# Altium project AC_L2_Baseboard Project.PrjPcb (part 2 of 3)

## Sheet AC_L2_Baseboard SCH-POL_PWR.SchDoc
size 431 x 279 mm; Date: Not shown in title block; ApprovedBy: Not shown in title block; CheckedBy: Not shown in title block; Author: Not shown in title block; CompanyName: Not shown in title block; Engineer: Not shown in title block; Organization: Not shown in title block; Address1: Not shown in title block; Address2: Not shown in title block; Address3: Not shown in title block; Address4: Not shown in title block; DocumentNumber: 3; Revision: Use project parameter SCH_Rev; SheetNumber: 3; SheetTotal: 11; PageSetup: Record=PageOptions¦CenterHorizontal=True¦CenterVertical=True¦PrintScale=1.00¦XCorrection=1.00¦YCorrection=1.00¦PrintKind=0¦BorderSize=5000000¦LeftOffset=0¦BottomOffset=0¦Orientation=2¦PaperLength=1000¦PaperWidth=1000¦Scale=100¦PaperSource=15¦PrintQuality=600¦MediaType=1¦DitherType=10¦PaperKind=Letter¦PrintScaleMode=1
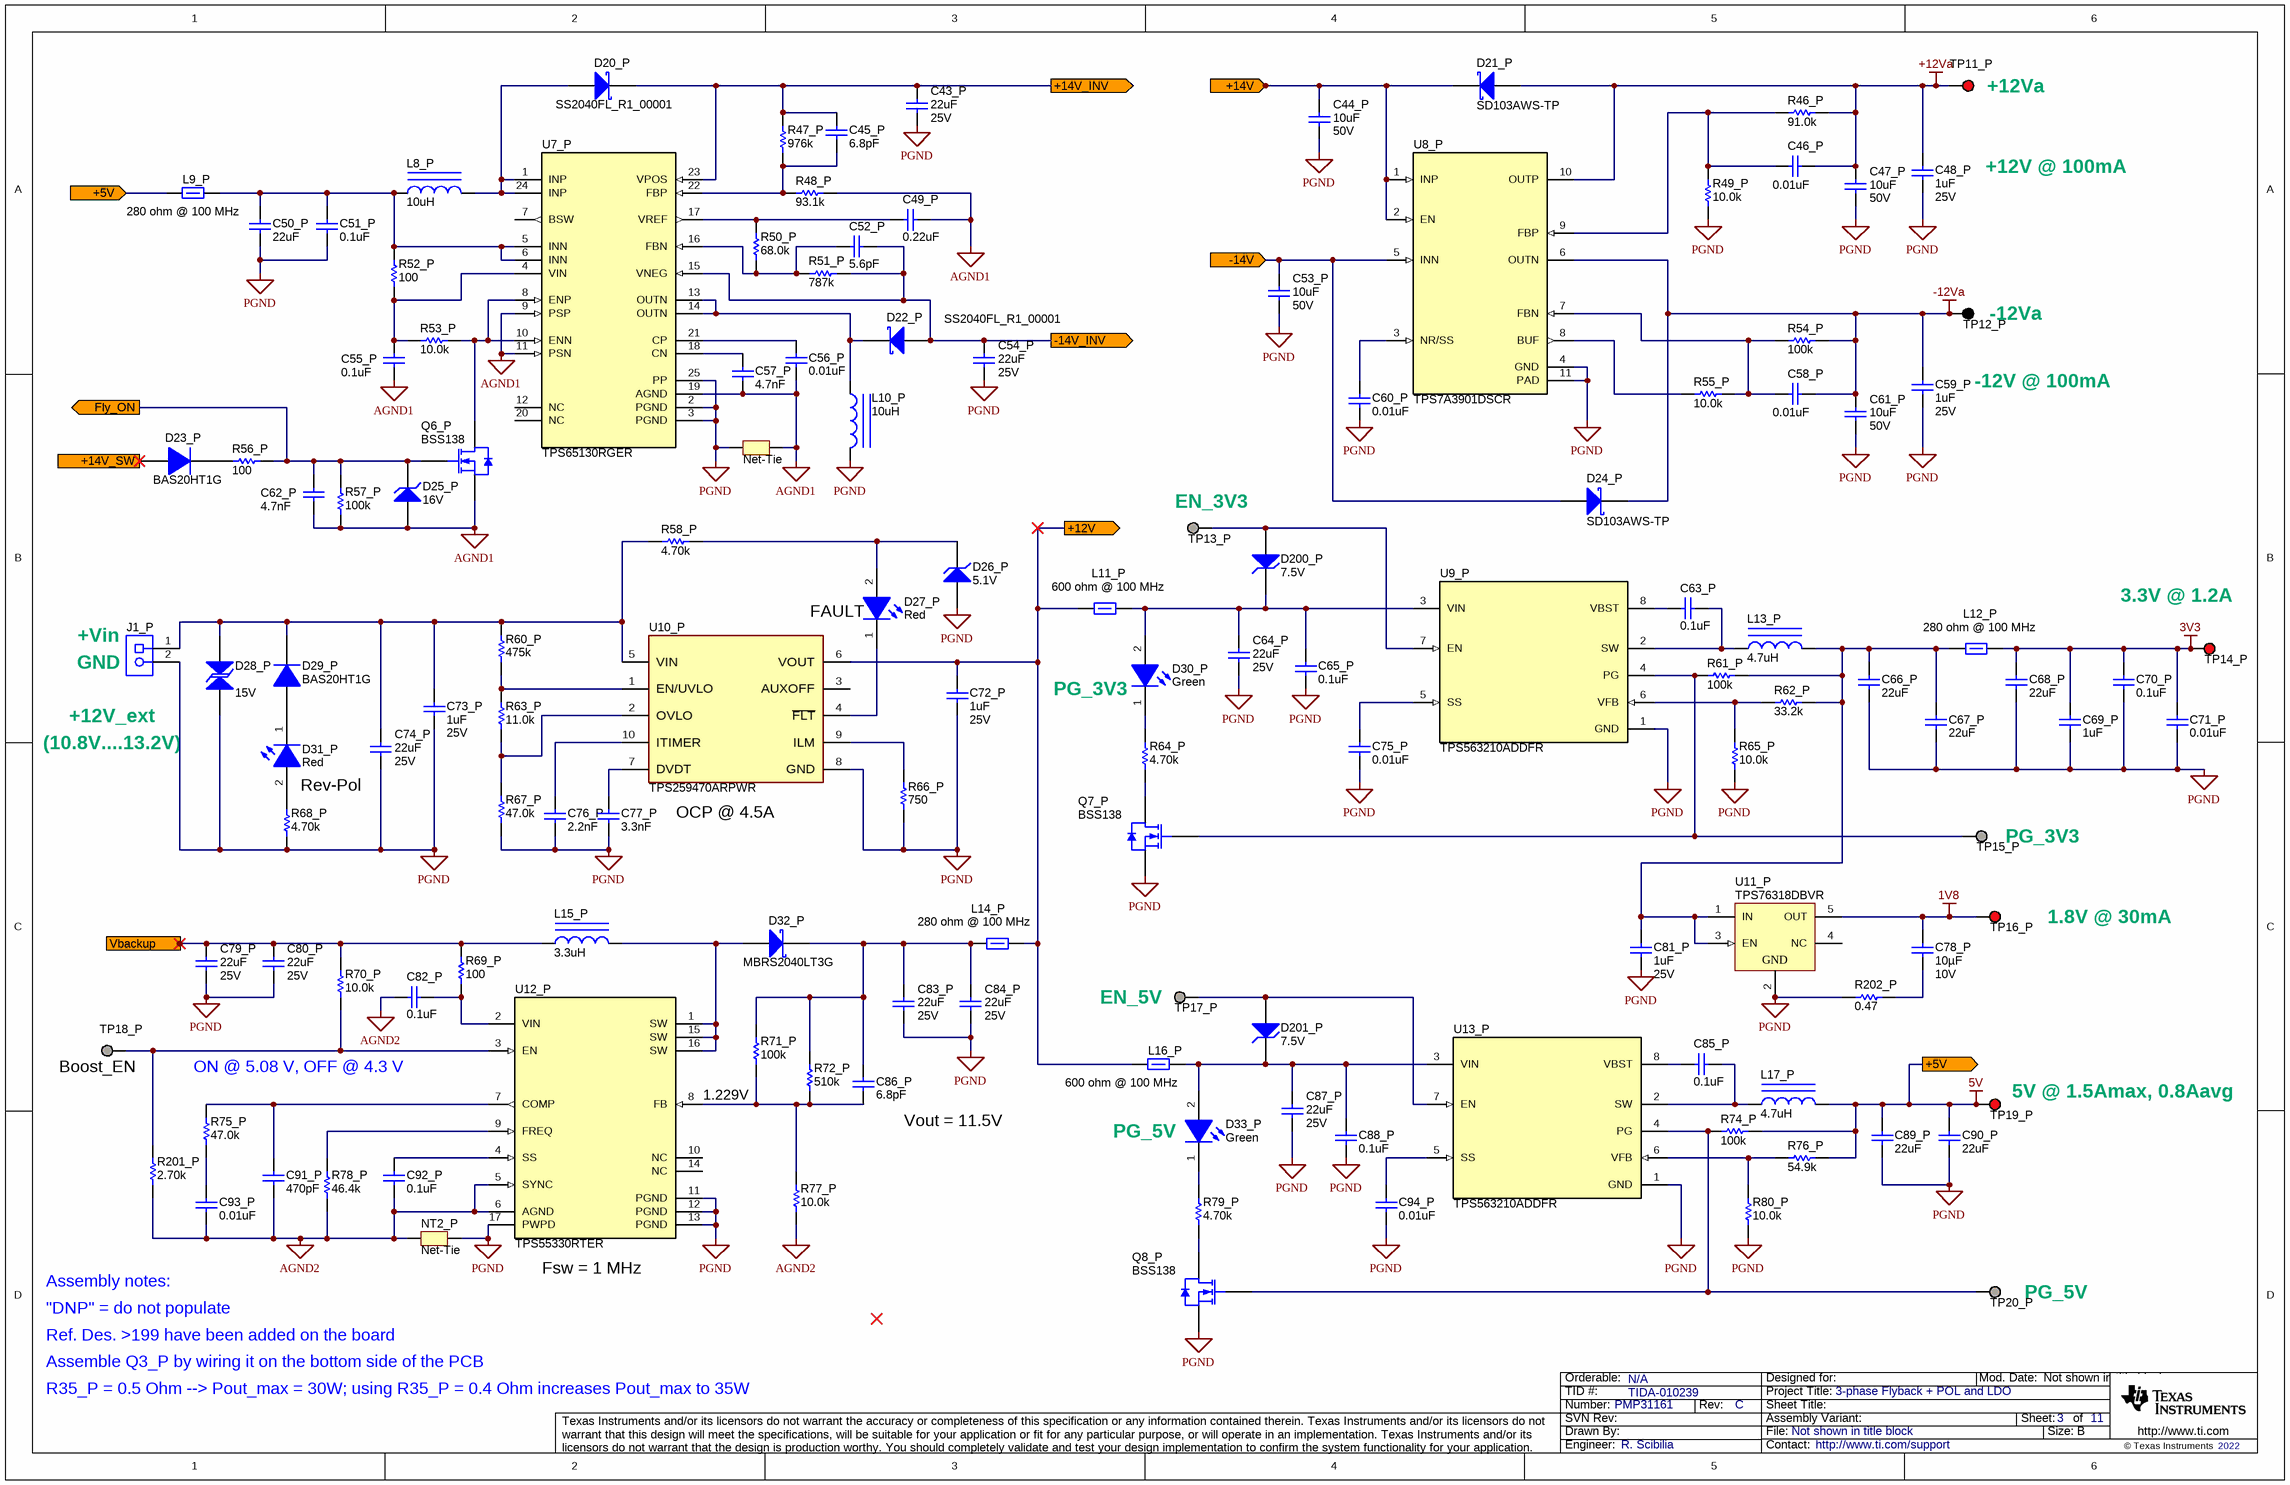
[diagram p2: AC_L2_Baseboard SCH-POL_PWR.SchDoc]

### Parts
C43_P  VDC_V: 25V  ValueDisplayed: 22uF  [1210_270]  (hidden comment: 885012109015)
C44_P  VDC_V: 50V  ValueDisplayed: 10uF  [1206]  (hidden comment: 885012108022)
C45_P  ValueDisplayed: 6.8pF  [0603]  (hidden comment: 885012006050)
C46_P  value 0.01uF  [0603]  (hidden comment: 885012206089)
C47_P  VDC_V: 50V  ValueDisplayed: 10uF  [1206]  (hidden comment: 885012108022)
C48_P  value 1uF  VDC_V: 25V  [0603]  (hidden comment: 885012206076)
C49_P  value 0.22uF  [0603]  (hidden comment: 885012206048)
C50_P  ValueDisplayed: 22uF  [1206_190]  (hidden comment: 885012208019)
C51_P  value 0.1uF  [0603]  (hidden comment: 885012206095)
C52_P  ValueDisplayed: 5.6pF  [0603]  (hidden comment: 885012006092)
C53_P  VDC_V: 50V  ValueDisplayed: 10uF  [1206]  (hidden comment: 885012108022)
C54_P  VDC_V: 25V  ValueDisplayed: 22uF  [1210_270]  (hidden comment: 885012109015)
C55_P  value 0.1uF  [0603]  (hidden comment: 885012206095)
C56_P  value 0.01uF  [0603]  (hidden comment: 885012206089)
C57_P  Cap_F: 4.7nF  [0603]  (hidden comment: 885012206087)
C58_P  value 0.01uF  [0603]  (hidden comment: 885012206089)
C59_P  value 1uF  VDC_V: 25V  [0603]  (hidden comment: 885012206076)
C60_P  value 0.01uF  [0603]  (hidden comment: 885012206089)
C61_P  VDC_V: 50V  ValueDisplayed: 10uF  [1206]  (hidden comment: 885012108022)
C62_P  Cap_F: 4.7nF  [0603]  (hidden comment: 885012206087)
C63_P  value 0.1uF  [0603]  (hidden comment: 885012206095)
C64_P  VDC_V: 25V  ValueDisplayed: 22uF  [1210_270]  (hidden comment: 885012109015)
C65_P  value 0.1uF  [0603]  (hidden comment: 885012206095)
C66_P  ValueDisplayed: 22uF  [1206_190]  (hidden comment: 885012208019)
C67_P  ValueDisplayed: 22uF  [1206_190]  (hidden comment: 885012208019)
C68_P  ValueDisplayed: 22uF  [1206_190]  (hidden comment: 885012208019)
C69_P  value 1uF  [0603]  (hidden comment: 885012206076)
C70_P  value 0.1uF  [0603]  (hidden comment: 885012206095)
C71_P  value 0.01uF  [0603]  (hidden comment: 885012206089)
C72_P  value 1uF  VDC_V: 25V  [0603]  (hidden comment: 885012206076)
C73_P  value 1uF  VDC_V: 25V  [0603]  (hidden comment: 885012206076)
C74_P  VDC_V: 25V  ValueDisplayed: 22uF  [1210_270]  (hidden comment: 885012109015)
C75_P  value 0.01uF  [0603]  (hidden comment: 885012206089)
C76_P  Cap_F: 2.2nF  [0603]  (hidden comment: 885012206085)
C77_P  Cap_F: 3.3nF  [0603]  (hidden comment: 885012206111)
C78_P  ValueDisplayed: 10µF  VDC_V: 10V  [0603]  (hidden comment: GRM188R61A106KE69D)
C79_P  VDC_V: 25V  ValueDisplayed: 22uF  [1210_270]  (hidden comment: 885012109015)
C80_P  VDC_V: 25V  ValueDisplayed: 22uF  [1210_270]  (hidden comment: 885012109015)
C81_P  value 1uF  VDC_V: 25V  [0603]  (hidden comment: 885012206076)
C82_P  value 0.1uF  [0603]  (hidden comment: 885012206095)
C83_P  VDC_V: 25V  ValueDisplayed: 22uF  [1210_270]  (hidden comment: 885012109015)
C84_P  VDC_V: 25V  ValueDisplayed: 22uF  [1210_270]  (hidden comment: 885012109015)
C85_P  value 0.1uF  [0603]  (hidden comment: 885012206095)
C86_P  ValueDisplayed: 6.8pF  [0603]  (hidden comment: 885012006050)
C87_P  VDC_V: 25V  ValueDisplayed: 22uF  [1210_270]  (hidden comment: 885012109015)
C88_P  value 0.1uF  [0603]  (hidden comment: 885012206095)
C89_P  ValueDisplayed: 22uF  [1206_190]  (hidden comment: 885012208019)
C90_P  ValueDisplayed: 22uF  [1206_190]  (hidden comment: 885012208019)
C91_P  Cap_F: 470pF  [0603]  (hidden comment: 885012206081)
C92_P  value 0.1uF  [0603]  (hidden comment: 885012206095)
C93_P  value 0.01uF  [0603]  (hidden comment: 885012206089)
C94_P  value 0.01uF  [0603]  (hidden comment: 885012206089)
D20_P  SS2040FL_R1_00001  [SOD-123FL]
D21_P  SD103AWS-TP  [SOD-323]
D22_P  SS2040FL_R1_00001  [SOD-123FL]
D23_P  BAS20HT1G  [SOD-323]
D24_P  SD103AWS-TP  [SOD-323]
D25_P  value 16V  [SOD-323]  (hidden comment: SZMM3Z16VST1G)
D26_P  value 5.1V  [SOD-323]  (hidden comment: BZT52C5V1S-7-F)
D27_P  value Red  [WL_SMCW_RED_1206]  (hidden comment: 150120RS75000)
D28_P  value 15V  [SMA_Bi]  (hidden comment: SMAJ15CA)
D29_P  BAS20HT1G  [SOD-323]
D30_P  value Green  [WL_SMCW_RED_1206]  (hidden comment: 150120GS75000)
D31_P  value Red  [WL_SMCW_RED_1206]  (hidden comment: 150120RS75000)
D32_P  MBRS2040LT3G  [SMB]
D33_P  value Green  [WL_SMCW_RED_1206]  (hidden comment: 150120GS75000)
D200_P  value 7.5V  [SOD-323]  (hidden comment: MM3Z7V5ST1G)
D201_P  value 7.5V  [SOD-323]  (hidden comment: MM3Z7V5ST1G)
J1_P  691214110002  [Wurth_691214110002]  (value not drawn)
L8_P  ValueDisplayed: 10uH  [WE-TPC-M1]  (hidden comment: 744042100)
L9_P  value 280 ohm @ 100 MHz  [1206]  (hidden comment: 74279221281)
L10_P  ValueDisplayed: 10uH  [WE-TPC-M1]  (hidden comment: 744042100)
L11_P  value 600 ohm @ 100 MHz  [1206_180]  (hidden comment: 74279221601)
L12_P  value 280 ohm @ 100 MHz  [1206]  (hidden comment: 74279221281)
L13_P  ValueDisplayed: 4.7uH  [WE-HC4]  (hidden comment: 744311470)
L14_P  value 280 ohm @ 100 MHz  [1206]  (hidden comment: 74279221281)
L15_P  ValueDisplayed: 3.3uH  [XEL4030_310]  (hidden comment: XEL4030-332MEB)
L16_P  value 600 ohm @ 100 MHz  [1206_180]  (hidden comment: 74279221601)
L17_P  ValueDisplayed: 4.7uH  [WE-HC4]  (hidden comment: 744311470)
NT1_P  Net-Tie  [Net-Tie_10mil]  (net tie, no BOM)
NT2_P  Net-Tie  [Net-Tie_10mil]  (net tie, no BOM)
Q6_P  BSS138  [SOT-23]
Q7_P  BSS138  [SOT-23]
Q8_P  BSS138  [SOT-23]
R46_P  ValueDisplayed: 91.0k  [0603]  (hidden comment: RC0603FR-0791KL)
R47_P  ValueDisplayed: 976k  [0603]  (hidden comment: CRCW0603976KFKEA)
R48_P  ValueDisplayed: 93.1k  [0603]  (hidden comment: CRCW060393K1FKEA)
R49_P  ValueDisplayed: 10.0k  [0603]  (hidden comment: RC0603FR-0710KL)
R50_P  ValueDisplayed: 68.0k  [0603]  (hidden comment: RC0603FR-0768KL)
R51_P  ValueDisplayed: 787k  [0603]  (hidden comment: RC0603FR-07787KL)
R52_P  ValueDisplayed: 100  [0603]  (hidden comment: CRCW0603100RFKEA)
R53_P  ValueDisplayed: 10.0k  [0603]  (hidden comment: RC0603FR-0710KL)
R54_P  ValueDisplayed: 100k  [0603]  (hidden comment: CRCW0603100KFKEA)
R55_P  ValueDisplayed: 10.0k  [0603]  (hidden comment: RC0603FR-0710KL)
R56_P  ValueDisplayed: 100  [0805_HV]  (hidden comment: CRCW0805100RFKEA)
R57_P  ValueDisplayed: 100k  [0603]  (hidden comment: CRCW0603100KFKEA)
R58_P  ValueDisplayed: 4.70k  [0603]  (hidden comment: RC0603FR-074K7L)
R60_P  ValueDisplayed: 475k  [0603]  (hidden comment: CRCW0603475KFKEA)
R61_P  ValueDisplayed: 100k  [0603S]  (hidden comment: CRCW0603100KFKEA)
R62_P  ValueDisplayed: 33.2k  [0603]  (hidden comment: RC0603FR-0733K2L)
R63_P  ValueDisplayed: 11.0k  [0603]  (hidden comment: RMCF0603FT11K0)
R64_P  ValueDisplayed: 4.70k  [0603]  (hidden comment: RC0603FR-074K7L)
R65_P  ValueDisplayed: 10.0k  [0603]  (hidden comment: RC0603FR-0710KL)
R66_P  ValueDisplayed: 750  [0603]  (hidden comment: CRCW0603750RFKEA)
R67_P  ValueDisplayed: 47.0k  [0603]  (hidden comment: RC0603FR-0747KL)
R68_P  ValueDisplayed: 4.70k  [0603]  (hidden comment: RC0603FR-074K7L)
R69_P  ValueDisplayed: 100  [0603]  (hidden comment: CRCW0603100RFKEA)
R70_P  ValueDisplayed: 10.0k  [0603]  (hidden comment: RC0603FR-0710KL)
R71_P  ValueDisplayed: 100k  [0603]  (hidden comment: RC0603FR-07100KL)
R72_P  ValueDisplayed: 510k  [0603]  (hidden comment: RC0603FR-07510KL)
R74_P  ValueDisplayed: 100k  [0603]  (hidden comment: CRCW0603100KFKEA)
R75_P  ValueDisplayed: 47.0k  [0603]  (hidden comment: RC0603FR-0747KL)
R76_P  ValueDisplayed: 54.9k  [0603]  (hidden comment: RC0603FR-0754K9L)
R77_P  ValueDisplayed: 10.0k  [0603]  (hidden comment: RC0603FR-0710KL)
R78_P  ValueDisplayed: 46.4k  [0603]  (hidden comment: RT0603DRE0746K4L)
R79_P  ValueDisplayed: 4.70k  [0603]  (hidden comment: RC0603FR-074K7L)
R80_P  ValueDisplayed: 10.0k  [0603]  (hidden comment: RC0603FR-0710KL)
R201_P  ValueDisplayed: 2.70k  [0603]  (hidden comment: RC0603FR-072K7L)
R202_P  ValueDisplayed: 0.47  [0603]  (hidden comment: ERJ-3RQFR47V)
TP11_P  5000  [Keystone5000]  (value not drawn)
TP12_P  5001  [Keystone5001]  (value not drawn)
TP13_P  TP_SM_1MM  [TP_SM_1MM]  (value not drawn)  (no BOM)
TP14_P  5010  [Keystone5010]  (value not drawn)
TP15_P  TP_SM_1MM  [TP_SM_1MM]  (value not drawn)  (no BOM)
TP16_P  5010  [Keystone5010]  (value not drawn)
TP17_P  TP_SM_1MM  [TP_SM_1MM]  (value not drawn)  (no BOM)
TP18_P  TP_SM_1MM  [TP_SM_1MM]  (value not drawn)  (no BOM)
TP19_P  5010  [Keystone5010]  (value not drawn)
TP20_P  TP_SM_1MM  [TP_SM_1MM]  (value not drawn)  (no BOM)
U7_P  TPS65130RGER  [RGE0024B]
U8_P  TPS7A3901DSCR  [DSC0010J]
U9_P  TPS563210ADDFR  [DDF0008A_N]
U10_P  TPS259470ARPWR  [RPW0010A-MFG]
U11_P  TPS76318DBVR  [DBV0005A_N]
U12_P  TPS55330RTER  [RTE0016C_NV]
U13_P  TPS563210ADDFR  [DDF0008A_N]

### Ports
+5V (in), +5V (out), +12V (out), +14V (in), +14V_INV (out), +14V_SW (in), -14V (in), -14V_INV (out), Fly_ON (out), Vbackup (in)

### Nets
1V8: C78_P.1 TP16_P.1 U11_P.5(OUT)
3V3: C68_P.1 C69_P.1 C70_P.1 C71_P.2 L12_P.2 TP14_P.1
5V: C89_P.1 C90_P.1 L9_P.1 L17_P.2 R74_P.2 R76_P.2 TP19_P.1 ; port +5V
+12Va: C46_P.2 C47_P.1 C48_P.1 D21_P.2(A) R46_P.1 TP11_P.1 U8_P.10(OUTP)
-12Va: C58_P.2 C59_P.1 C61_P.1 D24_P.1(K) R54_P.2 TP12_P.1 U8_P.6(OUTN)
AGND1: C49_P.1 C55_P.2 C56_P.1 C57_P.2 C62_P.2 D25_P.2(A) NT1_P.2 Q6_P.2(S) R48_P.2 R57_P.1 U7_P.9(PSP) U7_P.11(PSN) U7_P.19(AGND)
AGND2: C82_P.1 C91_P.2 C92_P.2 C93_P.1 NT2_P.1 R77_P.1 R78_P.1 R201_P.1 U12_P.5(SYNC) U12_P.6(AGND)
PGND: C43_P.2 C44_P.2 C47_P.2 C48_P.2 C50_P.2 C51_P.2 C53_P.2 C54_P.2 C59_P.2 C60_P.1 C61_P.2 C64_P.2 C65_P.2 C66_P.2 C67_P.2 C68_P.2 C69_P.2 C70_P.2 C71_P.1 C72_P.2 C73_P.2 C74_P.2 C75_P.1 C76_P.2 C77_P.2 C79_P.2 C80_P.2 C81_P.2 C83_P.2 C84_P.2 C87_P.2 C88_P.2 C89_P.2 C90_P.2 C94_P.1 D26_P.2(A) D28_P.1 J1_P.2 L10_P.2 NT1_P.1 NT2_P.2 Q7_P.2(S) Q8_P.2(S) R49_P.1 R65_P.1 R66_P.1 R67_P.1 R68_P.1 R80_P.1 R202_P.1 U7_P.2(PGND) U7_P.3(PGND) U7_P.25(PP) U8_P.4(GND) U8_P.11(PAD) U9_P.1(GND) U10_P.8(GND) U11_P.2(GND) U12_P.11(PGND) U12_P.12(PGND) U12_P.13(PGND) U12_P.17(PWPD) U13_P.1(GND)
+12V: C72_P.1 L11_P.1 L14_P.2 L16_P.1 U10_P.6(VOUT) ; port +12V
+14V: C44_P.1 D21_P.1(K) U8_P.1(INP) U8_P.2(EN) ; port +14V
+14V_INV: C43_P.1 C45_P.1 D20_P.1(K) R47_P.2 U7_P.23(VPOS) ; port +14V_INV
+14V_SW: D23_P.2(A) ; port +14V_SW
-14V: C53_P.1 D24_P.2(A) U8_P.5(INN) ; port -14V
-14V_INV: C52_P.1 C54_P.1 D22_P.2(A) R51_P.2 U7_P.15(VNEG) ; port -14V_INV
Fly_ON: C62_P.1 D25_P.1(K) Q6_P.1(G) R56_P.2 R57_P.2 ; port Fly_ON
Vbackup: C79_P.1 C80_P.1 L15_P.1 R69_P.2 R70_P.2 ; port Vbackup
NetC45_P_2: C45_P.2 R47_P.1 R48_P.1 U7_P.22(FBP)
NetC46_P_1: C46_P.1 R46_P.2 R49_P.2 U8_P.9(FBP)
NetC49_P_2: C49_P.2 R50_P.2 U7_P.17(VREF)
NetC50_P_1: C50_P.1 C51_P.1 L8_P.1 L9_P.2 R52_P.2 U7_P.5(INN) U7_P.6(INN)
NetC52_P_2: C52_P.2 R50_P.1 R51_P.1 U7_P.16(FBN)
NetC55_P_1: C55_P.1 R52_P.1 R53_P.2 U7_P.4(VIN)
NetC56_P_2: C56_P.2 U7_P.21(CP)
NetC57_P_1: C57_P.1 U7_P.18(CN)
NetC58_P_1: C58_P.1 R54_P.1 R55_P.2 U8_P.7(FBN)
NetC60_P_2: C60_P.2 U8_P.3(NR/SS)
NetC63_P_1: C63_P.1 U9_P.8(VBST)
NetC63_P_2: C63_P.2 L13_P.1 U9_P.2(SW)
NetC64_P_1: C64_P.1 C65_P.1 D30_P.2(A) D200_P.1(K) L11_P.2 U9_P.3(VIN)
NetC66_P_1: C66_P.1 C67_P.1 C81_P.1 L12_P.1 L13_P.2 R61_P.2 R62_P.2 U11_P.1(IN) U11_P.3(EN)
NetC73_P_1: C73_P.1 C74_P.1 D28_P.2 D29_P.1(K) J1_P.1 R58_P.2 R60_P.2 U10_P.5(VIN)
NetC75_P_2: C75_P.2 U9_P.5(SS)
NetC76_P_1: C76_P.1 U10_P.10(ITIMER)
NetC77_P_1: C77_P.1 U10_P.7(DVDT)
NetC78_P_2: C78_P.2 R202_P.2
NetC82_P_2: C82_P.2 R69_P.1 U12_P.2(VIN)
NetC83_P_1: C83_P.1 C84_P.1 C86_P.1 D32_P.1(K) L14_P.1 R71_P.2 R72_P.2
NetC85_P_1: C85_P.1 U13_P.8(VBST)
NetC85_P_2: C85_P.2 L17_P.1 U13_P.2(SW)
NetC86_P_2: C86_P.2 R71_P.1 R72_P.1 R77_P.2 U12_P.8(FB)
NetC87_P_1: C87_P.1 C88_P.1 D33_P.2(A) D201_P.1(K) L16_P.2 U13_P.3(VIN)
NetC91_P_1: C91_P.1 R75_P.2 U12_P.7(COMP)
NetC92_P_1: C92_P.1 U12_P.4(SS)
NetC93_P_2: C93_P.2 R75_P.1
NetC94_P_2: C94_P.2 U13_P.5(SS)
NetD20_P_2: D20_P.2(A) L8_P.2 U7_P.1(INP) U7_P.24(INP)
NetD22_P_1: D22_P.1(K) L10_P.1 U7_P.13(OUTN) U7_P.14(OUTN)
NetD23_P_1: D23_P.1(K) R56_P.1
NetD26_P_1: D26_P.1(K) D27_P.2(A) R58_P.1
NetD27_P_1: D27_P.1(K) U10_P.4(~{FLT})
NetD29_P_2: D29_P.2(A) D31_P.1(K)
NetD30_P_1: D30_P.1(K) R64_P.2
NetD31_P_2: D31_P.2(A) R68_P.2
NetD32_P_2: D32_P.2(A) L15_P.2 U12_P.1(SW) U12_P.15(SW) U12_P.16(SW)
NetD33_P_1: D33_P.1(K) R79_P.2
NetD200_P_2: D200_P.2(A) TP13_P.1 U9_P.7(EN)
NetD201_P_2: D201_P.2(A) TP17_P.1 U13_P.7(EN)
NetQ6_P_3: Q6_P.3(D) R53_P.1 U7_P.8(ENP) U7_P.10(ENN)
NetQ7_P_1: Q7_P.1(G) R61_P.1 TP15_P.1 U9_P.4(PG)
NetQ7_P_3: Q7_P.3(D) R64_P.1
NetQ8_P_1: Q8_P.1(G) R74_P.1 TP20_P.1 U13_P.4(PG)
NetQ8_P_3: Q8_P.3(D) R79_P.1
NetR55_P_1: R55_P.1 U8_P.8(BUF)
NetR60_P_1: R60_P.1 R63_P.2 U10_P.1(EN/UVLO)
NetR62_P_1: R62_P.1 R65_P.2 U9_P.6(VFB)
NetR63_P_1: R63_P.1 R67_P.2 U10_P.2(OVLO)
NetR66_P_2: R66_P.2 U10_P.9(ILM)
NetR70_P_1: R70_P.1 R201_P.2 TP18_P.1 U12_P.3(EN)
NetR76_P_1: R76_P.1 R80_P.2 U13_P.6(VFB)
NetR78_P_2: R78_P.2 U12_P.9(FREQ)

Not connected (* = marked no-connect by the designer): U7_P 7(BSW) 12(NC) 20(NC); U10_P 3(AUXOFF); U11_P 4(NC); U12_P 10(NC) 14(NC)

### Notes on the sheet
- (near TP11_P) +12Va
- +12V @ 100mA
- (near TP12_P) -12Va
- -12V @ 100mA
- (near TP13_P) EN_3V3
- (near J1_P) +Vin
- FAULT
- (near TP14_P) 3.3V @ 1.2A
- (near J1_P) GND
- (near D30_P) PG_3V3
- (near J1_P) +12V_ext
- (10.8V....13.2V)
- Rev-Pol
- (near U10_P) OCP @ 4.5A
- (near TP15_P) PG_3V3
- 1.8V @ 30mA
- (near TP17_P) EN_5V
- (near TP18_P) Boost_EN
- ON @ 5.08 V, OFF @ 4.3 V
- 1.229V
- (near TP19_P) 5V @ 1.5Amax, 0.8Aavg
- (near C86_P) Vout = 11.5V
- (near D33_P) PG_5V
- Assembly notes:
- (near U12_P) Fsw = 1 MHz
- (near TP20_P) PG_5V
- Ref. Des. >199 have been added on the board
- Assemble Q3_P by wiring it on the bottom side of the PCB
- "DNP" = do not populate
- R35_P = 0.5 Ohm --> Pout_max = 30W; using R35_P = 0.4 Ohm increases Pout_max to 35W

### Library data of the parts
C43_P C54_P C64_P C74_P C79_P C80_P C83_P C84_P C87_P = CMP-0009224-2: CAP, CERM, 22 uF, 25 V, +/- 20%, X5R, 1210; Manufacturer: Wuerth; TaMin_C: -55°C; Polarized: N; SizeAreaWB_mm2: 14.7; Value1: Unknown; U/M: EA; Value: 22uF; TaMax_C: 85°C; SizeZ_mm: 2.7; SizeX_mm: 3.2; SizeY_mm: 2.5; Cap_Case: 1210; SizeArea_mm2: 8; Cap_F: 22µF; AEC Category: Q200
C44_P C47_P C53_P C61_P = CMP-0008821-2: CAP, CERM, 10 uF, 50 V, +/- 10%, X7R, 1206; Manufacturer: Wuerth; TaMin_C: -55°C; Polarized: N; SizeAreaWB_mm2: 10.92; Value1: Unknown; U/M: EA; Value: 10uF; TaMax_C: 125°C; SizeZ_mm: 1.35; SizeX_mm: 3.2; SizeY_mm: 1.6; SizeArea_mm2: 5.12; Cap_F: 10µF; AEC Category: Q200
C45_P C86_P = CMP-0006798-4: CAP, CERM, 6.8 pF, 50 V, +/- 4%, C0G/NP0, 0603; Manufacturer: Wuerth; TaMin_C: -55°C; ESR_ohm: 0.505; Polarized: N; SizeAreaWB_mm2: 4.68; Value1: 0.505 ohm; U/M: EA; Value: 6.8pF; TaMax_C: 125°C; SizeZ_mm: 1; SizeX_mm: 1.6; SizeY_mm: 0.8; Value2: 50V; SizeArea_mm2: 1.28; AEC Category: Q200
C46_P C56_P C58_P C60_P C71_P C75_P C93_P C94_P = CMP-0006854-4: CAP, CERM, 0.01 uF, 50 V, +/- 10%, X7R, 0603; Manufacturer: Wuerth; TaMin_C: -55°C; Polarized: N; SizeAreaWB_mm2: 4.68; U/M: EA; TaMax_C: 125°C; SizeZ_mm: 1; SizeX_mm: 1.6; SizeY_mm: 0.8; Value2: 50V; SizeArea_mm2: 1.28; Cap_F: 10nF; AEC Category: Q200
C48_P C59_P C72_P C73_P C81_P = CMP-0083856-1: CAP, CERM, 1 µF, 25 V,+/- 10%, X7R, 0603; Manufacturer: Wuerth; TaMin_C: -55°C; Polarized: N; SizeAreaWB_mm2: 4.68; U/M: EA; TaMax_C: 125°C; SizeZ_mm: 1; SizeX_mm: 1.6; SizeY_mm: 0.8; SizeArea_mm2: 1.28; Cap_F: 1µF; AEC Category: Q200
C49_P = CMP-0007389-4: CAP, CERM, 0.22 uF, 16 V, +/- 10%, X7R, 0603; Manufacturer: Wuerth; TaMin_C: -55°C; Polarized: N; SizeAreaWB_mm2: 4.68; Value1: Unknown; U/M: EA; TaMax_C: 125°C; SizeZ_mm: 1; SizeX_mm: 1.6; SizeY_mm: 0.8; Value2: 16V; SizeArea_mm2: 1.28; Cap_F: 220nF; AEC Category: Q200
C50_P C66_P C67_P C68_P C89_P C90_P = CMP-0064937-2: CAP, CERM, 22 uF, 10 V,+/- 10%, X7R, 1206; Manufacturer: Wurth Elektronik; TaMin_C: -55°C; Polarized: N; SizeAreaWB_mm2: 10.92; Value1: Unknown; U/M: EA; Value: 22uF; TaMax_C: 125°C; SizeZ_mm: 1.9; SizeX_mm: 3.2; SizeY_mm: 1.6; Cap_Case: 1206; Value2: 10V; SizeArea_mm2: 5.12; Cap_F: 22µF; AEC Category: Q200
C51_P C55_P C63_P C65_P C70_P C82_P C85_P C88_P C92_P = CMP-0007044-5: CAP, CERM, 0.1 uF, 50 V, +/- 10%, X7R, 0603; Manufacturer: Wuerth; TaMin_C: -55°C; ESR_ohm: 29.6m; Polarized: N; SizeAreaWB_mm2: 4.68; Value1: 0.0296 ohm; U/M: EA; TaMax_C: 125°C; SizeZ_mm: 1; SizeX_mm: 1.6; SizeY_mm: 0.8; Value2: 50V; SizeArea_mm2: 1.28; Cap_F: 100nF; IRMS_A: 971.99mA; AEC Category: Q200
C52_P = CMP-0006795-4: CAP, CERM, 5.6 pF, 50 V, +/- 5%, C0G/NP0, 0603; Manufacturer: Wuerth; TaMin_C: -55°C; ESR_ohm: 0.568; Polarized: N; SizeAreaWB_mm2: 4.68; Value1: 0.568 ohm; U/M: EA; Value: 5.6pF; TaMax_C: 125°C; SizeZ_mm: 1; SizeX_mm: 1.6; SizeY_mm: 0.8; Value2: 50V; SizeArea_mm2: 1.28; AEC Category: Q200
C57_P C62_P = CMP-0006835-4: CAP, CERM, 4700 pF, 50 V, +/- 10%, X7R, 0603; Manufacturer: Wurth Elektronik; TaMin_C: -55°C; Polarized: N; SizeAreaWB_mm2: 4.68; Value1: Unknown; U/M: EA; Value: 4700pF; TaMax_C: 125°C; SizeZ_mm: 1; SizeX_mm: 1.6; SizeY_mm: 0.8; Value2: 50V; SizeArea_mm2: 1.28; AEC Category: Q200
C69_P = CMP-0083856-1: CAP, CERM, 1 µF, 25 V,+/- 10%, X7R, 0603; Manufacturer: Wuerth; TaMin_C: -55°C; Polarized: N; SizeAreaWB_mm2: 4.68; U/M: EA; TaMax_C: 125°C; SizeZ_mm: 1; SizeX_mm: 1.6; SizeY_mm: 0.8; Value2: 25V; SizeArea_mm2: 1.28; Cap_F: 1µF; AEC Category: Q200
C76_P = CMP-0006897-4: CAP, CERM, 2200 pF, 50 V, +/- 10%, X7R, 0603; Manufacturer: Wuerth; TaMin_C: -55°C; Polarized: N; SizeAreaWB_mm2: 4.68; Value1: Unknown; U/M: EA; Value: 2200pF; TaMax_C: 125°C; SizeZ_mm: 1; SizeX_mm: 1.6; SizeY_mm: 0.8; Value2: 50V; SizeArea_mm2: 1.28; AEC Category: Q200
C77_P = CMP-0006805-4: CAP, CERM, 3300 pF, 50 V, +/- 10%, X7R, 0603; Manufacturer: Wuerth; TaMin_C: -55°C; Polarized: N; SizeAreaWB_mm2: 4.68; Value1: Unknown; U/M: EA; Value: 3300pF; TaMax_C: 125°C; SizeZ_mm: 1; SizeX_mm: 1.6; SizeY_mm: 0.8; Value2: 50V; SizeArea_mm2: 1.28; AEC Category: Q200
C78_P = CMP-0085855-1: CAP, CERM, 10 µF, 10 V,+/- 10%, X5R, 0603; Manufacturer: MuRata; SizeX_mm: 1.6; SizeAreaWB_mm2: 4.68; Green_REACh: Incomplete; AEC Category: Q200; SizeArea_mm2: 1.28; SizeY_mm: 0.8; Green_Lifecycle: Active; TaMax_C: 85°C; Value: 10uF; U/M: EA; Polarized: N; TaMin_C: -55°C; SizeZ_mm: 1
C91_P = CMP-0006834-5: CAP, CERM, 470 pF, 50 V, +/- 10%, X7R, 0603; Manufacturer: Wurth Elektronik; TaMin_C: -55°C; Polarized: N; SizeAreaWB_mm2: 4.68; Value1: Unknown; U/M: EA; Value: 470pF; TaMax_C: 125°C; SizeZ_mm: 1; SizeX_mm: 1.6; SizeY_mm: 0.8; Value2: 50V; SizeArea_mm2: 1.28; AEC Category: Q200
D20_P D22_P = CMP-0028777-2: Diode, Schottky, 40 V, 2 A, SOD-123FL; Manufacturer: Panjit International Inc.; Green_REACh: Incomplete; SizeArea_mm2: 5.94; Value1: 2A; AEC Qualified: Y; Value2: 0.63V; SizeZ_mm: 0.98; SizeAreaWB_mm2: 12.19; Vr_V: 40V; SizeY_mm: 1.65; SizeX_mm: 3.6; TJmax_C: 150°C; Green_Lifecycle: Not Set; AEC Category: Q101; Vf_V: 630mV
D21_P D24_P = CMP-0076928-2: Diode, Schottky, 40 V, 0.35 A, SOD-323; Manufacturer: Micro Commercial Components; SizeX_mm: 2.7; Vr_V: 40V; SizeAreaWB_mm2: 8.695; AEC Category: Q101; Vf_V: 600mV; SizeArea_mm2: 3.645; Green_Lifecycle: Not Set; SizeY_mm: 1.35; Io_A: 350mA; SizeZ_mm: 1.0; Green_REACh: Incomplete; Value2: 0.6V; Value1: 0.35A
D23_P D29_P = CMP-0029150-2: Diode, Switching, 200 V, 0.2 A, AEC-Q101, SOD-323; Manufacturer: ON Semiconductor; Value2: 1.25V; Value1: 0.2A; SizeZ_mm: 1; Green_REACh: Incomplete; SizeArea_mm2: 3.645; Vr_V: 200V; SizeX_mm: 2.7; TJmax_C: 150°C; Io_A: 200mA; Green_Lifecycle: Not Set; SizeAreaWB_mm2: 8.695; AEC Qualified: Y; AEC Category: Q101; SizeY_mm: 1.35
D25_P = CMP-0085759-1: Diode, Zener, 16 V, 300 mW, AEC-Q101, SOD-323; Manufacturer: ON Semiconductor; AEC Category: Q101; RJA_CperW: 416; SizeX_mm: 2.7; SizeAreaWB_mm2: 8.695; SizeZ_mm: 1; SizeArea_mm2: 3.645; AEC Qualified: Y; SizeY_mm: 1.35; Value1: 0.3W; Power_W: 300mW
D26_P = CMP-0005865-3: Diode, Zener, 5.1 V, 200 mW, SOD-323; Manufacturer: Diodes Inc.; SizeY_mm: 1.35; SizeX_mm: 2.7; RJA_CperW: 625; AEC Category: Q101; SizeArea_mm2: 3.645; Value1: 0.2W; SizeZ_mm: 1; SizeAreaWB_mm2: 8.695; Power_W: 200mW
D27_P D31_P = CMP-0002935-3: LED, Red, SMD; Manufacturer: Wurth Elektronik; Vf_V: 2V; Angle: 140; Value1: 0.072W; Vr_V: 5V; Io_A: 20mA; Tjmax_C: 85°C; Type: AlInGaP; Power_TotalModule: 72mW; Ir_A: 10µA
D28_P = CMP-0085006-1: Diode, TVS, Bi, 15 V, 24.4 Vc, 400 W, 16.4 A, SMA (non-polarized); Manufacturer: Littelfuse; RJA_CperW: 120; Vbr_Min: 16.7V; Value1: 24.4V; SizeAreaWB_mm2: 32.368125; Green_Lifecycle: Active; SizeArea_mm2: 13.068125; AEC Category: Q101; SizeX_mm: 5.075; SizeY_mm: 2.575; AEC Qualified: N; Ipp: 16.4A; Ppk: 400W; SizeZ_mm: 2.65; Green_REACh: Incomplete; Vbr_Max: 18.5V
D30_P D33_P = CMP-0002935-3: LED, Green, SMD; Manufacturer: Wurth Elektronik; Vf_V: 2V; Angle: 140; Value1: 0.072W; Vr_V: 5V; Io_A: 20mA; Tjmax_C: 85°C; Type: AlInGaP; Power_TotalModule: 72mW; Ir_A: 10µA
D32_P = CMP-0028529-2: Diode, Schottky, 40 V, 2 A, SMB; Manufacturer: ON Semiconductor; TJmax_C: 125°C; AEC Category: Q101; SizeY_mm: 3.81; Io_A: 2A; SizeX_mm: 5.6; Vf_V: 430mV; RJC_CperW: 22.5; Vr_V: 40V; SizeAreaWB_mm2: 44.156; SizeZ_mm: 2.6; Green_Lifecycle: Active; SizeArea_mm2: 21.336; Value2: 0.43V; Value: 40V; Green_REACh: Passed
D200_P D201_P = CMP-0085747-1: Diode, Zener, 7.5 V, 300 mW, SOD-323; Manufacturer: ON Semiconductor; AEC Category: Q101; Power_W: 300mW; RJA_CperW: 416; AEC Qualified: N; SizeArea_mm2: 3.645; SizeX_mm: 2.7; SizeY_mm: 1.35; SizeZ_mm: 1; SizeAreaWB_mm2: 8.695; Value1: 0.3W
J1_P = CMP-0054825-2: Terminal Block, 3.5mm, 2x1, Tin, TH; Manufacturer: Wurth Elektronik; Pitch_mm: 3.5; CT: TRUE; CNHeader: FALSE; Voltage_V: 300V; Gender: Female; Cert_UL: Y; Row_Count: 1; Current_A: 10A
L8_P L10_P = CMP-0063804-1: Inductor, Shielded Drum Core, Ferrite, 10 uH, 1 A, 0.12 ohm, SMD; Manufacturer: Wurth Elektronik; Isat: 1A @ 35% inductance drop; Irms: 1.3A @ 30C rise; Green_Lifecycle: Active; SizeAreaWB_mm2: 33.64; DCR_ohm: 0.12; Green_REACh: Passed; Value: 10uH; Imax_A: 1A; SizeZ_mm: 1.8; SizeX_mm: 4.8; SizeArea_mm2: 23.04; Ind_H: 10µH; AEC Category: Q200
L9_P L12_P L14_P = CMP-0003140-1: Ferrite Bead, 280 ohm @ 100 MHz, 3.5 A, 1206; Manufacturer: Wurth Elektronik; Ztyp@1GHz_Ohm: 79.415; ZTyp@100MHz_Ohm: 280; SizeAreaWB_mm2: 10.92; DCR_ohm: 22m; Value1: 0.022 ohm; Imax_A: 3.5A; SizeZ_mm: 1.35; SizeX_mm: 3.2; SizeY_mm: 1.6; SizeArea_mm2: 5.12; ValueDisplayed: 280 ohm
L11_P L16_P = CMP-0086103-1: Ferrite Bead, 600 ohm @ 100 MHz, 2.5 A, 1206; Manufacturer: Wuerth; DCR_ohm: 38m; SizeZ_mm: 1.8; Value1: 0.038 ohm; SizeAreaWB_mm2: 10.92; ZTyp@100MHz_Ohm: 600; SizeY_mm: 1.6; SizeArea_mm2: 5.12; Imax_A: 2.5A; SizeX_mm: 3.2; ValueDisplayed: 600 ohm
L13_P L17_P = CMP-0063928-1: Inductor, Shielded Drum Core, Superflux, 4.7 uH, 6 A, 0.02 ohm, SMD; Manufacturer: Wurth Elektronik; Isat: 7A @ 30% inductance drop; Irms: 6A @ 50C rise; Green_Lifecycle: Active; SizeAreaWB_mm2: 80.1; DCR_ohm: 20m; Green_REACh: Passed; Value: 4.7uH; Imax_A: 6A; SizeZ_mm: 4; SizeX_mm: 7; SizeY_mm: 6.9; SizeArea_mm2: 48.3; Ind_H: 4.7µH; AEC Category: Q200
L15_P = CMP-0061090-1: Inductor, Shielded, 3.3 uH, 5 A, 0.0286 ohm, SMD; Manufacturer: Coilcraft; Isat: 5.9A @ 30% inductance drop; Irms: 5A @ 20C rise; SizeAreaWB_mm2: 25; DCR_ohm: 28.6m; Value: 3.3uH; Imax_A: 5A; SizeZ_mm: 3.1; SizeX_mm: 4; SizeArea_mm2: 16; Ind_H: 3.3µH; AEC Qualified: N; AEC Category: Q200
NT1_P NT2_P = CMP-0078142-2: Single point connection between nets.
Q6_P Q7_P Q8_P = CMP-0000755-1: MOSFET, N-CH, 50 V, 0.22 A, SOT-23; Alternate Manufacturer: None; Manufacturer: Fairchild Semiconductor; SizeZ_mm: 1.1; ChType: N; Value2: 1.7 nC; VdsMax_V: 50V; SizeX_mm: 2.5; SizeY_mm: 3; Vgs_V: 20V; Rdson45_ohm: 6; SizeArea_mm2: 7.5; AEC Category: Q101; IdsMax_A: 220mA; SizeAreaWB_mm2: 14; U/M: EA; QgTyp_nC: 1.7
R46_P = CMP-0023318-5: RES, 91.0 k, 1%, 0.1 W, 0603; Manufacturer: Yageo; Power_W: 100mW; TempCo: 100 ppm/C; Value_Code: 91k0; Value: 91.0k; Res_ohm: 91k; SizeX_mm: 1.6; SizeY_mm: 0.8; SizeZ_mm: 1; Value2: 0.1W; SizeArea_mm2: 1.28; AEC Qualified: N; VDC_V: 75V; AEC Category: Q200; SizeAreaWB_mm2: 4.68
R47_P = CMP-0022661-3: RES, 976 k, 1%, 0.1 W, AEC-Q200 Grade 0, 0603; Manufacturer: Vishay-Dale; Power_W: 100mW; TempCo: 100 ppm/C; Value: 976k; EIA_Code: E96; SizeX_mm: 1.6; SizeY_mm: 0.8; SizeZ_mm: 1; Value2: 0.1W; SizeArea_mm2: 1.28; AEC Qualified: Y; VDC_V: 75V; AEC Category: Q200; AEC Grade: 0
R48_P = CMP-0022655-4: RES, 93.1 k, 1%, 0.1 W, AEC-Q200 Grade 0, 0603; Manufacturer: Vishay-Dale; Power_W: 100mW; TempCo: 100 ppm/C; Value_Code: 93k1; Value: 93.1k; EIA_Code: E96; SizeX_mm: 1.6; SizeY_mm: 0.8; SizeZ_mm: 1; Value2: 0.1W; SizeArea_mm2: 1.28; AEC Qualified: Y; VDC_V: 75V; AEC Category: Q200; AEC Grade: 0
R49_P R53_P R55_P R65_P R70_P R77_P R80_P = CMP-0022746-5: RES, 10.0 k, 1%, 0.1 W, 0603; Manufacturer: Yageo; Power_W: 100mW; TempCo: 100 ppm/C; Value_Code: 10k0; Value: 10.0k; EIA_Code: E96; Res_ohm: 10k; SizeX_mm: 1.6; SizeY_mm: 0.8; SizeZ_mm: 1; Value2: 0.1W; SizeArea_mm2: 1.28; AEC Qualified: N; VDC_V: 75V; AEC Category: Q200; SizeAreaWB_mm2: 4.68
R50_P = CMP-0023239-5: RES, 68.0 k, 1%, 0.1 W, 0603; Manufacturer: Yageo; Power_W: 100mW; TempCo: 100 ppm/C; Value_Code: 68k0; Value: 68.0k; Res_ohm: 68k; SizeX_mm: 1.6; SizeY_mm: 0.8; SizeZ_mm: 1; Value2: 0.1W; SizeArea_mm2: 1.28; AEC Qualified: N; VDC_V: 75V; AEC Category: Q200; SizeAreaWB_mm2: 4.68
R51_P = CMP-0023273-4: RES, 787 k, 1%, 0.1 W, 0603; Manufacturer: Yageo; Power_W: 100mW; TempCo: 100 ppm/C; Value: 787k; EIA_Code: E96; SizeX_mm: 1.6; SizeY_mm: 0.8; SizeZ_mm: 1; Value2: 0.1W; SizeArea_mm2: 1.28; AEC Qualified: N; VDC_V: 75V; AEC Category: Q200; SizeAreaWB_mm2: 4.68
R52_P R69_P = CMP-0021991-4: RES, 100, 1%, 0.1 W, AEC-Q200 Grade 0, 0603; Manufacturer: Vishay-Dale; Power_W: 100mW; TempCo: 100 ppm/C; Value_Code: 100R; Value: 100; EIA_Code: E96; SizeX_mm: 1.6; SizeY_mm: 0.8; SizeZ_mm: 1; Value2: 0.1W; SizeArea_mm2: 1.28; AEC Qualified: Y; VDC_V: 75V; AEC Category: Q200; AEC Grade: 0
R54_P R57_P R61_P R74_P = CMP-0021990-4: RES, 100 k, 1%, 0.1 W, AEC-Q200 Grade 0, 0603; Manufacturer: Vishay-Dale; Power_W: 100mW; TempCo: 100 ppm/C; Value: 100k; EIA_Code: E96; SizeX_mm: 1.6; SizeY_mm: 0.8; SizeZ_mm: 1; Value2: 0.1W; SizeArea_mm2: 1.28; AEC Qualified: Y; VDC_V: 75V; AEC Category: Q200; AEC Grade: 0
R56_P = CMP-0020835-3: RES, 100, 1%, 0.125 W, AEC-Q200 Grade 0, 0805; Manufacturer: Vishay-Dale; Power_W: 125mW; TempCo: 100 ppm/C; Value_Code: 100R; Value: 100; EIA_Code: E96; SizeX_mm: 2; SizeY_mm: 1.25; SizeZ_mm: 1.45; Value2: 0.125W; SizeArea_mm2: 2.5; AEC Qualified: Y; VDC_V: 150V; AEC Category: Q200; AEC Grade: 0
R58_P R64_P R68_P R79_P = CMP-0023153-5: RES, 4.70 k, 1%, 0.1 W, 0603; Manufacturer: Yageo; Power_W: 100mW; TempCo: 100 ppm/C; Value_Code: 4k70; Value: 4.70k; Res_ohm: 4.7k; SizeX_mm: 1.6; SizeY_mm: 0.8; SizeZ_mm: 1; Value2: 0.1W; SizeArea_mm2: 1.28; AEC Qualified: N; VDC_V: 75V; AEC Category: Q200; SizeAreaWB_mm2: 4.68
R60_P = CMP-0022436-4: RES, 475 k, 1%, 0.1 W, AEC-Q200 Grade 0, 0603; Manufacturer: Vishay-Dale; Power_W: 100mW; TempCo: 100 ppm/C; Value: 475k; EIA_Code: E96; SizeX_mm: 1.6; SizeY_mm: 0.8; SizeZ_mm: 1; Value2: 0.1W; SizeArea_mm2: 1.28; AEC Qualified: Y; VDC_V: 75V; AEC Category: Q200; AEC Grade: 0
R62_P = CMP-0023036-5: RES, 33.2 k, 1%, 0.1 W, 0603; Manufacturer: Yageo; Power_W: 100mW; TempCo: 100 ppm/C; Value_Code: 33k2; Value: 33.2k; EIA_Code: E96; SizeX_mm: 1.6; SizeY_mm: 0.8; SizeZ_mm: 1; Value2: 0.1W; SizeArea_mm2: 1.28; AEC Qualified: N; VDC_V: 75V; AEC Category: Q200; SizeAreaWB_mm2: 4.68
R63_P = CMP-0023342-3: RES, 11.0 k, 1%, 0.1 W, AEC-Q200 Grade 0, 0603; Manufacturer: Stackpole Electronics Inc; Power_W: 100mW; TempCo: 100 ppm/C; Value_Code: 11k0; U/M: EA; Value: 11.0k; EIA_Code: E96; Res_ohm: 11k; SizeX_mm: 1.6; SizeY_mm: 0.8; SizeZ_mm: 1; Value2: 0.1W; SizeArea_mm2: 1.28; AEC Qualified: Y; VDC_V: 75V; AEC Grade: 0; AEC Category: Q200
R66_P = CMP-0022588-5: RES, 750, 1%, 0.1 W, AEC-Q200 Grade 0, 0603; Manufacturer: Vishay-Dale; Power_W: 100mW; TempCo: 100 ppm/C; Value_Code: 750R; Value: 750; EIA_Code: E96; SizeX_mm: 1.6; SizeY_mm: 0.8; SizeZ_mm: 1; Value2: 0.1W; SizeArea_mm2: 1.28; AEC Qualified: Y; VDC_V: 75V; AEC Category: Q200; AEC Grade: 0
R67_P R75_P = CMP-0023133-5: RES, 47.0 k, 1%, 0.1 W, 0603; Manufacturer: Yageo; Power_W: 100mW; TempCo: 100 ppm/C; Value_Code: 47k0; Value: 47.0k; Res_ohm: 47k; SizeX_mm: 1.6; SizeY_mm: 0.8; SizeZ_mm: 1; Value2: 0.1W; SizeArea_mm2: 1.28; AEC Qualified: N; VDC_V: 75V; AEC Category: Q200; SizeAreaWB_mm2: 4.68
R71_P = CMP-0022735-5: RES, 100 k, 1%, 0.1 W, 0603; Manufacturer: Yageo; Power_W: 100mW; TempCo: 100 ppm/C; Value: 100k; EIA_Code: E96; SizeX_mm: 1.6; SizeY_mm: 0.8; SizeZ_mm: 1; Value2: 0.1W; SizeArea_mm2: 1.28; AEC Qualified: N; VDC_V: 75V; AEC Category: Q200; SizeAreaWB_mm2: 4.68
R72_P = CMP-0023162-4: RES, 510 k, 1%, 0.1 W, 0603; Manufacturer: Yageo; Power_W: 100mW; TempCo: 100 ppm/C; Value: 510k; SizeX_mm: 1.6; SizeY_mm: 0.8; SizeZ_mm: 1; Value2: 0.1W; SizeArea_mm2: 1.28; AEC Qualified: N; VDC_V: 75V; AEC Category: Q200; SizeAreaWB_mm2: 4.68
R76_P = CMP-0023180-5: RES, 54.9 k, 1%, 0.1 W, 0603; Manufacturer: Yageo; Power_W: 100mW; TempCo: 100 ppm/C; Value_Code: 54k9; Value: 54.9k; EIA_Code: E96; SizeX_mm: 1.6; SizeY_mm: 0.8; SizeZ_mm: 1; Value2: 0.1W; SizeArea_mm2: 1.28; AEC Qualified: N; VDC_V: 75V; AEC Category: Q200; SizeAreaWB_mm2: 4.68
R78_P = CMP-0025309-3: RES, 46.4 k, 0.5%, 0.1 W, 0603; Manufacturer: Yageo America; Power_W: 100mW; TempCo: 50 ppm/C; Value_Code: 46k4; U/M: EA; Value: 46.4k; EIA_Code: E192; SizeX_mm: 1.6; SizeY_mm: 0.8; SizeZ_mm: 1; Value2: 0.1W; SizeArea_mm2: 1.28; VDC_V: 75V; AEC Category: Q200
R201_P = CMP-0022996-5: RES, 2.70 k, 1%, 0.1 W, 0603; Manufacturer: Yageo; Power_W: 100mW; TempCo: 100 ppm/C; Value_Code: 2k70; Value: 2.70k; Res_ohm: 2.7k; SizeX_mm: 1.6; SizeY_mm: 0.8; SizeZ_mm: 1; Value2: 0.1W; SizeArea_mm2: 1.28; AEC Qualified: N; VDC_V: 75V; AEC Category: Q200; SizeAreaWB_mm2: 4.68
R202_P = CMP-0022716-3: RES, 0.47, 1%, 0.1 W, AEC-Q200 Grade 0, 0603; Manufacturer: Panasonic; Power_W: 100mW; TempCo: 300 ppm/C; Value_Code: R470; Value: 0.47; EIA_Code: E96; SizeX_mm: 1.6; SizeY_mm: 0.8; SizeZ_mm: 1; Value2: 0.1W; SizeArea_mm2: 1.28; AEC Qualified: Y; AEC Category: Q200; AEC Grade: 0; SizeAreaWB_mm2: 4.68
TP11_P = CMP-0055137-2: Test Point, Miniature, Red, TH; Manufacturer: Keystone Electronics; Green_REACh: Passed; Green_Lifecycle: Active; ContactFinish: Silver; CNHeader: FALSE; CT: TRUE
TP12_P = CMP-0055138-2: Test Point, Miniature, Black, TH; Manufacturer: Keystone Electronics; ContactFinish: Silver; CNHeader: FALSE; Green_Lifecycle: Active; Green_REACh: Passed; CT: TRUE
TP13_P TP15_P TP17_P TP18_P TP20_P = CMP-0003825-1: 1mm Test Point, SMT; Manufacturer: Any
TP14_P TP16_P TP19_P = CMP-0055147-2: Test Point, Multipurpose, Red, TH; Manufacturer: Keystone Electronics; CT: TRUE; ContactFinish: Silver; Green_Lifecycle: Active; CNHeader: FALSE; Green_REACh: Passed
U7_P = CMP-0034952-2: Postive and Negative Output DC-DC Converter, 2.7 to 5.5 V, -40 to 85 degC, 24-pin QFN (RGE24), Green (RoHS & no Sb/Br); Manufacturer: Texas Instruments; SubFamily: LCD/OLED Display Bias Solutions; Rating: Catalog; Topology: Boost, Inverting Buck/Boost; Vin(Max)(V): 5.5; Vin(Min)(V): 2.7; Iq(Typ)(mA): 0.5; Switching Frequency(Typ)(kHz): 1400
U8_P = CMP-0013435-7: Dual, 150mA, Wide-Vin, Positive and Negative Low-Dropout (LDO) Voltage Regulator, DSC0010J (WSON-10); Alternate Manufacturer: Texas Instruments; Alternate PartNumber: TPS7A3901DSCT; Rating: Catalog; CompType: IC; SizeAreaWB_mm2: 16.0; SizeY_mm: 3.0; AEC Qualified: N; SizeZ_mm: 0.8; SizeArea_mm2: 9.0; AEC Category: Q200
U9_P U13_P = CMP-0013290-3: 17V Input, 3A Synchronous Step-Down Regulator in SOT-23 w/ Advanced Eco-mode™, PG, Soft Start, DDF0008A (SOT-23-THN-8); Alternate Manufacturer: Texas Instruments; Alternate PartNumber: TPS563210ADDFT; AEC Category: Q200; SizeZ_mm: 1.1; SizeAreaWB_mm2: 14.82; Rating: Catalog; CompType: IC; SizeX_mm: 2.8; AEC Qualified: N; SizeY_mm: 2.9; SizeArea_mm2: 8.12
U10_P = CMP-0091660-1: 2.7 - 23 V, 5.5 A, 28 mΩ True Reverse Current Blocking eFuse with Input Reverse Polarity Protection; Manufacturer: Texas Instruments; Min Supply Voltage: 2.7V; TJmax_C: +125°C; Nominal Supply Current: 428uA; Max Supply Voltage: 23V; SizeZ_mm: 1mm; AEC Qualified: No; Standoff Height: 0mm; Number Of Outputs: 1
U11_P = CMP-0035639-1: Single Output LDO, 150 mA, Fixed 1.8 V Output, 2.7 to 10 V Input, with Low IQ, 5-pin SOT-23 (DBV), -40 to 125 degC, Green (RoHS & no Sb/Br); Manufacturer: Texas Instruments; Vin(Max)(V): 10; SubFamily: Single Channel LDO; Vout Adj(Min)(V): 1.8; Accuracy(%): 3; Iq(Typ)(mA): 0.08; Iout(Max)(A): 0.15; Vin(Min)(V): 2.7; Vdo(Typ)(mV): 300
U12_P = CMP-0067160-2: Integrated 5-A 24-V Wide Input Range Boost/SEPIC/Flyback DC-DC Regulator, RTE0016C (WQFN-16); Alternate PartNumber: TPS55330RTET; Manufacturer: Texas Instruments; SizeZ_mm: 0.8; SizeX_mm: 3.0; SizeArea_mm2: 9.0; CompType: IC; U/M: EA; SizeAreaWB_mm2: 16.0

## Sheet AC_L2_Baseboard_Relay_Weld_Detect.SchDoc
size 431 x 279 mm; Date: Not shown in title block; ApprovedBy: Not shown in title block; CheckedBy: Not shown in title block; Author: Not shown in title block; CompanyName: Not shown in title block; Engineer: Not shown in title block; Organization: Not shown in title block; Address1: Not shown in title block; Address2: Not shown in title block; Address3: Not shown in title block; Address4: Not shown in title block; DocumentNumber: 4; Revision: Use project parameter SCH_Rev; SheetNumber: 4; SheetTotal: 11; PageSetup: Record=PageOptions¦CenterHorizontal=True¦CenterVertical=True¦PrintScale=1.00¦XCorrection=1.00¦YCorrection=1.00¦PrintKind=0¦BorderSize=5000000¦LeftOffset=0¦BottomOffset=0¦Orientation=2¦PaperLength=1000¦PaperWidth=1000¦Scale=100¦PaperSource=15¦PrintQuality=600¦MediaType=1¦DitherType=10¦PaperKind=Letter¦PrintScaleMode=1
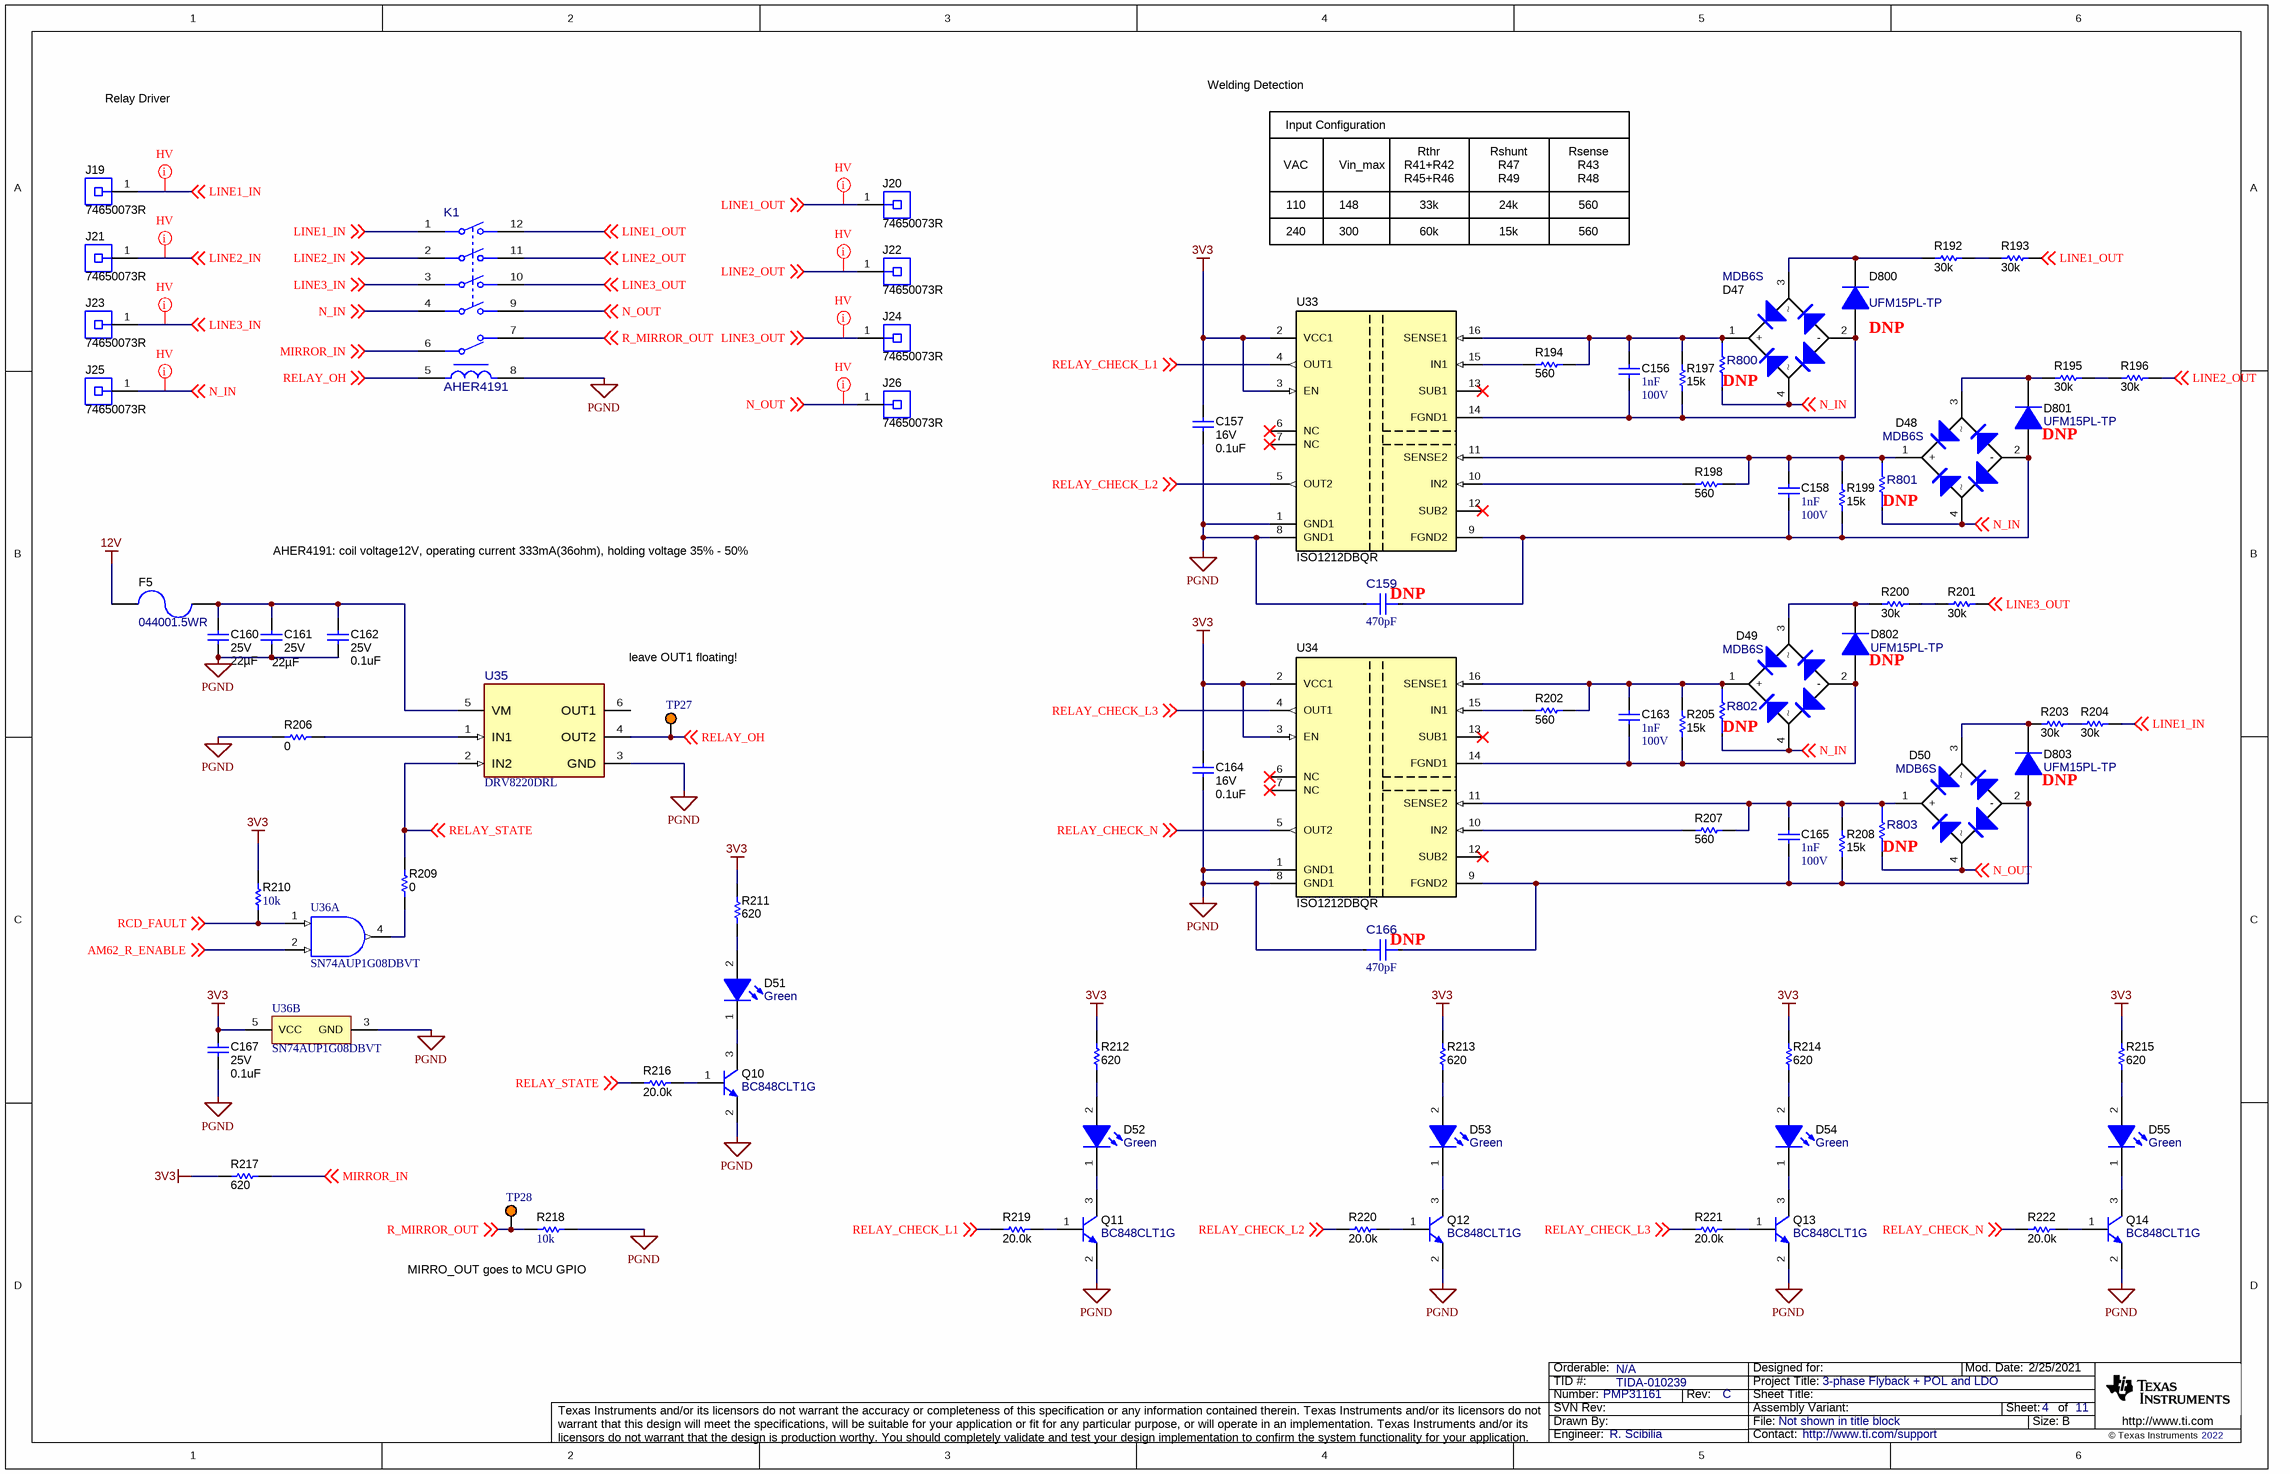
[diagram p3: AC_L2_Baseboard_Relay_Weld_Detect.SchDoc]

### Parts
C156  Cap_F: 1nF  VDC_V: 100V  [0603]  (hidden comment: CGA3E2X7R2A102K080AA)
C157  VDC_V: 16V  ValueDisplayed: 0.1uF  [0603]  (hidden comment: C0603C104K4RACTU)
C158  Cap_F: 1nF  VDC_V: 100V  [0603]  (hidden comment: CGA3E2X7R2A102K080AA)
C159  ValueDisplayed: 470pF  [FP-Q07E1D471KN0B0S0N0_RADIAL-MFG]  (hidden comment: Q07E1D471KN0B0S0N0)
C160  VDC_V: 25V  ValueDisplayed: 22µF  [1210_270]  (hidden comment: CC1210KKX7R8BB226)
C161  VDC_V: 25V  ValueDisplayed: 22µF  [1210_270]  (hidden comment: CC1210KKX7R8BB226)
C162  VDC_V: 25V  ValueDisplayed: 0.1uF  [0402S]  (hidden comment: TMK105B7104MV-FR)
C163  Cap_F: 1nF  VDC_V: 100V  [0603]  (hidden comment: CGA3E2X7R2A102K080AA)
C164  VDC_V: 16V  ValueDisplayed: 0.1uF  [0603]  (hidden comment: C0603C104K4RACTU)
C165  Cap_F: 1nF  VDC_V: 100V  [0603]  (hidden comment: CGA3E2X7R2A102K080AA)
C166  ValueDisplayed: 470pF  [FP-Q07E1D471KN0B0S0N0_RADIAL-MFG]  (hidden comment: Q07E1D471KN0B0S0N0)
C167  VDC_V: 25V  ValueDisplayed: 0.1uF  [0402S]  (hidden comment: TMK105B7104MV-FR)
D47  MDB6S  [MICRODIP_4]
D48  MDB6S  [MICRODIP_4]
D49  MDB6S  [MICRODIP_4]
D50  MDB6S  [MICRODIP_4]
D51  value Green  [WL-SMCW_GREEN]  (hidden comment: 150060GS75000)
D52  value Green  [WL-SMCW_GREEN]  (hidden comment: 150060GS75000)
D53  value Green  [WL-SMCW_GREEN]  (hidden comment: 150060GS75000)
D54  value Green  [WL-SMCW_GREEN]  (hidden comment: 150060GS75000)
D55  value Green  [WL-SMCW_GREEN]  (hidden comment: 150060GS75000)
D800  UFM15PL-TP  [SOD-123FL]
D801  UFM15PL-TP  [SOD-123FL]
D802  UFM15PL-TP  [SOD-123FL]
D803  UFM15PL-TP  [SOD-123FL]
F5  044001.5WR  [1206]
J19  74650073R  [Wurth_WP-THRBU]
J20  74650073R  [Wurth_WP-THRBU]
J21  74650073R  [Wurth_WP-THRBU]
J22  74650073R  [Wurth_WP-THRBU]
J23  74650073R  [Wurth_WP-THRBU]
J24  74650073R  [Wurth_WP-THRBU]
J25  74650073R  [Wurth_WP-THRBU]
J26  74650073R  [Wurth_WP-THRBU]
K1  AHER4191  [FP-AHER4191_PTH_RELAY_35MM0_58MM0-MFG]
Q10  BC848CLT1G  [SOT-23]
Q11  BC848CLT1G  [SOT-23]
Q12  BC848CLT1G  [SOT-23]
Q13  BC848CLT1G  [SOT-23]
Q14  BC848CLT1G  [SOT-23]
R192  ValueDisplayed: 30k  [1206]  (hidden comment: CRCW120630K0JNEA)
R193  ValueDisplayed: 30k  [1206]  (hidden comment: CRCW120630K0JNEA)
R194  ValueDisplayed: 560  [0603]  (hidden comment: RC0603JR-07560RL)
R195  ValueDisplayed: 30k  [1206]  (hidden comment: CRCW120630K0JNEA)
R196  ValueDisplayed: 30k  [1206]  (hidden comment: CRCW120630K0JNEA)
R197  ValueDisplayed: 15k  [0603]  (hidden comment: CRCW060315K0JNEA)
R198  ValueDisplayed: 560  [0603]  (hidden comment: RC0603JR-07560RL)
R199  ValueDisplayed: 15k  [0603]  (hidden comment: CRCW060315K0JNEA)
R200  ValueDisplayed: 30k  [1206]  (hidden comment: CRCW120630K0JNEA)
R201  ValueDisplayed: 30k  [1206]  (hidden comment: CRCW120630K0JNEA)
R202  ValueDisplayed: 560  [0603]  (hidden comment: RC0603JR-07560RL)
R203  ValueDisplayed: 30k  [1206]  (hidden comment: CRCW120630K0JNEA)
R204  ValueDisplayed: 30k  [1206]  (hidden comment: CRCW120630K0JNEA)
R205  ValueDisplayed: 15k  [0603]  (hidden comment: CRCW060315K0JNEA)
R206  ValueDisplayed: 0  [0603]  (hidden comment: RCS06030000Z0EA)
R207  ValueDisplayed: 560  [0603]  (hidden comment: RC0603JR-07560RL)
R208  ValueDisplayed: 15k  [0603]  (hidden comment: CRCW060315K0JNEA)
R209  ValueDisplayed: 0  [0603]  (hidden comment: RCS06030000Z0EA)
R210  ValueDisplayed: 10k  [0603]  (hidden comment: RC0603JR-0710KL)
R211  ValueDisplayed: 620  [0603]  (hidden comment: RC0603FR-07620RL)
R212  ValueDisplayed: 620  [0603]  (hidden comment: RC0603FR-07620RL)
R213  ValueDisplayed: 620  [0603]  (hidden comment: RC0603FR-07620RL)
R214  ValueDisplayed: 620  [0603]  (hidden comment: RC0603FR-07620RL)
R215  ValueDisplayed: 620  [0603]  (hidden comment: RC0603FR-07620RL)
R216  ValueDisplayed: 20.0k  [0603]  (hidden comment: ERJ-3EKF2002V)
R217  ValueDisplayed: 620  [0603]  (hidden comment: RC0603FR-07620RL)
R218  ValueDisplayed: 10k  [0603]  (hidden comment: RC0603JR-0710KL)
R219  ValueDisplayed: 20.0k  [0603]  (hidden comment: ERJ-3EKF2002V)
R220  ValueDisplayed: 20.0k  [0603]  (hidden comment: ERJ-3EKF2002V)
R221  ValueDisplayed: 20.0k  [0603]  (hidden comment: ERJ-3EKF2002V)
R222  ValueDisplayed: 20.0k  [0603]  (hidden comment: ERJ-3EKF2002V)
R800  RC0805FR-070RL  [FP-RC0805FR-070RL_0805-MFG]  (value not drawn)
R801  RC0805FR-070RL  [FP-RC0805FR-070RL_0805-MFG]  (value not drawn)
R802  RC0805FR-070RL  [FP-RC0805FR-070RL_0805-MFG]  (value not drawn)
R803  RC0805FR-070RL  [FP-RC0805FR-070RL_0805-MFG]  (value not drawn)
TP27  5003  [Keystone5003]  (value not drawn)
TP28  5003  [Keystone5003]  (value not drawn)
U33  ISO1212DBQR  [DBQ0016A_N]
U34  ISO1212DBQR  [DBQ0016A_N]
U35  DRV8220DRL  [DRL0006A-MFG]
U36  SN74AUP1G08DBVT  [DBV0005A_N]  (parts A,B of 2)

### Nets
3V3: C157.1 C164.1 C167.1 R210.2 R211.2 R212.2 R213.2 R214.2 R215.2 R217.2 U33.2(VCC1) U33.3(EN) U34.2(VCC1) U34.3(EN) U36.5(VCC)
12V: F5.2  [project net 12V_In]
PGND: C157.2 C159.1 C160.2 C161.2 C162.2 C164.2 C166.1 C167.2 K1.8 Q10.2(E) Q11.2(E) Q12.2(E) Q13.2(E) Q14.2(E) R206.2 R218.2 U33.1(GND1) U33.8(GND1) U34.1(GND1) U34.8(GND1) U35.3(GND) U36.3(GND)
AM62_R_ENABLE: U36.2(B) ; off-sheet AM62_R_ENABLE
LINE1_IN: J19.1 K1.1 R204.2 ; off-sheet LINE1_IN
LINE1_OUT: J20.1 K1.12 R193.2 ; off-sheet LINE1_OUT
LINE2_IN: J21.1 K1.2 ; off-sheet LINE2_IN
LINE2_OUT: J22.1 K1.11 R196.2 ; off-sheet LINE2_OUT
LINE3_IN: J23.1 K1.3 ; off-sheet LINE3_IN
LINE3_OUT: J24.1 K1.10 R201.2 ; off-sheet LINE3_OUT
MIRROR_IN: K1.6 R217.1 ; off-sheet MIRROR_IN
N_IN: D47.4 D48.4 D49.4 J25.1 K1.4 R800.1 R801.1 R802.1 ; off-sheet N_IN
N_OUT: D50.4 J26.1 K1.9 R803.2 ; off-sheet N_OUT
R_MIRROR_OUT: K1.7 R218.1 TP28.1 ; off-sheet R_MIRROR_OUT
RCD_FAULT: R210.1 U36.1(A) ; off-sheet RCD_FAULT
RELAY_CHECK_L1: R219.1 U33.4(OUT1) ; off-sheet RELAY_CHECK_L1
RELAY_CHECK_L2: R220.1 U33.5(OUT2) ; off-sheet RELAY_CHECK_L2
RELAY_CHECK_L3: R221.1 U34.4(OUT1) ; off-sheet RELAY_CHECK_L3
RELAY_CHECK_N: R222.1 U34.5(OUT2) ; off-sheet RELAY_CHECK_N
RELAY_OH: K1.5 TP27.1 U35.4(OUT2) ; off-sheet RELAY_OH
RELAY_STATE: R209.2 R216.1 U35.2(IN2) ; off-sheet RELAY_STATE
NetC156_1: C156.1 D47.1(+) R194.2 R197.2 R800.2 U33.16(SENSE1)
NetC156_2: C156.2 D47.2(-) D800.2(A) R197.1 U33.14(FGND1)
NetC158_1: C158.1 D48.1(+) R198.2 R199.2 R801.2 U33.11(SENSE2)
NetC158_2: C158.2 C159.2 D48.2(-) D801.2(A) R199.1 U33.9(FGND2)
NetC160_1: C160.1 C161.1 C162.1 F5.1 U35.5(VM)
NetC163_1: C163.1 D49.1(+) R202.2 R205.2 R802.2 U34.16(SENSE1)
NetC163_2: C163.2 D49.2(-) D802.2(A) R205.1 U34.14(FGND1)
NetC165_1: C165.1 D50.1(+) R207.2 R208.2 R803.1 U34.11(SENSE2)
NetC165_2: C165.2 C166.2 D50.2(-) D803.2(A) R208.1 U34.9(FGND2)
NetD47_3: D47.3 D800.1(K) R192.1
NetD48_3: D48.3 D801.1(K) R195.1
NetD49_3: D49.3 D802.1(K) R200.1
NetD50_3: D50.3 D803.1(K) R203.1
NetD51_1: D51.1(K) Q10.3(C)
NetD51_2: D51.2(A) R211.1
NetD52_1: D52.1(K) Q11.3(C)
NetD52_2: D52.2(A) R212.1
NetD53_1: D53.1(K) Q12.3(C)
NetD53_2: D53.2(A) R213.1
NetD54_1: D54.1(K) Q13.3(C)
NetD54_2: D54.2(A) R214.1
NetD55_1: D55.1(K) Q14.3(C)
NetD55_2: D55.2(A) R215.1
NetQ10_1: Q10.1(B) R216.2
NetQ11_1: Q11.1(B) R219.2
NetQ12_1: Q12.1(B) R220.2
NetQ13_1: Q13.1(B) R221.2
NetQ14_1: Q14.1(B) R222.2
NetR192_2: R192.2 R193.1
NetR194_1: R194.1 U33.15(IN1)
NetR195_2: R195.2 R196.1
NetR198_1: R198.1 U33.10(IN2)
NetR200_2: R200.2 R201.1
NetR202_1: R202.1 U34.15(IN1)
NetR203_2: R203.2 R204.1
NetR206_1: R206.1 U35.1(IN1)
NetR207_1: R207.1 U34.10(IN2)
NetR209_1: R209.1 U36.4(Y)

Not connected (* = marked no-connect by the designer): U33 6(NC)* 7(NC)* 12(SUB2)* 13(SUB1)*; U34 6(NC)* 7(NC)* 12(SUB2)* 13(SUB1)*; U35 6(OUT1)

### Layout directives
net class HV: LINE1_IN, LINE1_OUT, LINE2_IN, LINE2_OUT, LINE3_IN, LINE3_OUT, N_IN, N_OUT

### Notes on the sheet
- Relay Driver
- Welding Detection
- VAC
- Input Configuration
- Vin_max
- Rthr
- R41+R42
- Rshunt
- R47
- Rsense
- R43
- 110
- 240
- 148
- 300
- R45+R46
- 33k
- 60k
- R49
- 24k
- 15k
- R48
- 560
- (near D800) DNP
- DNP
- (near D801) DNP
- AHER4191: coil voltage12V, operating current 333mA(36ohm), holding voltage 35% - 50%
- (near R801) DNP
- (near C159) DNP
- leave OUT1 floating!
- (near D802) DNP
- (near D803) DNP
- (near R803) DNP
- (near C166) DNP
- MIRRO_OUT goes to MCU GPIO

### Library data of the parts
C156 C158 C163 C165 = CMP-0007081-2: CAP, CERM, 1000 pF, 100 V, +/- 10%, X7R, AEC-Q200 Grade 1, 0603; Manufacturer: TDK; TaMin_C: -55°C; ESR_ohm: 1.97137; Polarized: N; SizeAreaWB_mm2: 4.68; Value1: 1.97137 ohm; U/M: EA; Value: 1000pF; TaMax_C: 125°C; SizeZ_mm: 1; SizeX_mm: 1.6; SizeY_mm: 0.8; SizeArea_mm2: 1.28; AEC Qualified: Y; IRMS_A: 305.705mA; AEC Category: Q200
C157 C164 = CMP-0006860-5: CAP, CERM, 0.1 uF, 16 V, +/- 10%, X7R, 0603; Manufacturer: Kemet; TaMin_C: -55°C; Polarized: N; SizeAreaWB_mm2: 4.68; Value1: Unknown; U/M: EA; Value: 0.1uF; TaMax_C: 125°C; SizeZ_mm: 1; SizeX_mm: 1.6; SizeY_mm: 0.8; SizeArea_mm2: 1.28; Cap_F: 100nF; AEC Category: Q200
C159 C166 = CMP-0094642-1: 470 pF ±10% 400V Ceramic Capacitor Y5U (E) Radial, Disc; Manufacturer: Songtian Electronic; TempCo: -56/+22%; Value: 470pF; AEC Qualified: No; SizeZ_mm: 9.5mm
C160 C161 = CMP-0082267-1: CAP, CERM, 22 µF, 25 V,+/- 10%, X7R, 1210; Manufacturer: Yageo; TaMin_C: -55°C; ESR_ohm: 1m; Polarized: N; SizeAreaWB_mm2: 14.7; Value1: 0.001 ohm; U/M: EA; Value: 22uF; TaMax_C: 125°C; SizeZ_mm: 2.7; SizeX_mm: 3.2; SizeY_mm: 2.5; Cap_Case: 1210; SizeArea_mm2: 8; AEC Category: Q200
C162 C167 = CMP-0006720-2: CAP, CERM, 0.1 uF, 25 V, +/- 20%, X7R, 0402; Manufacturer: Taiyo Yuden; TaMin_C: -55°C; Polarized: N; SizeAreaWB_mm2: 3; Value1: Unknown; U/M: EA; Value: 0.1uF; TaMax_C: 125°C; SizeZ_mm: 0.6; SizeX_mm: 1; SizeY_mm: 0.5; Cap_Case: 0402; Cap_F: 100nF; AEC Category: Q200
D47-D50 = CMP-0029231-3: Diode, Switching-Bridge, 600 V, 1 A, MICRODIP_4; Manufacturer: Fairchild Semiconductor; Vr_V: 600V; AEC Category: Q101; Io_A: 1A; Green_Lifecycle: Not Set; Green_REACh: Incomplete; SizeY_mm: 5; SizeZ_mm: 1.45; SizeArea_mm2: 32.5; Value: 600V; SizeX_mm: 6.5; TJmax_C: 150°C; SizeAreaWB_mm2: 59.5; Value2: 1.1V
D51-D55 = CMP-0002905-2: LED, Green, SMD; Manufacturer: Wurth Elektronik; Type: InGaN; Vf_V: 3.2V; Io_A: 20mA; Tjmax_C: 85°C; Value1: W; Angle: 140
D800-D803 = CMP-0029148-2: Diode, Ultrafast, 600 V, 1 A, SOD-123FL; Manufacturer: Micro Commercial Components; SizeY_mm: 1.65; Value: 600V; Io_A: 1A; Green_Lifecycle: Not Set; Green_REACh: Incomplete; SizeX_mm: 3.6; SizeAreaWB_mm2: 12.19; SizeArea_mm2: 5.94; AEC Qualified: N; Value2: 1.7V; SizeZ_mm: 0.98; AEC Category: Q101; TJmax_C: 150°C
F5 = CMP-0003461-2: Fuse, 1.5 A, 50VAC/VDC, SMD; Manufacturer: Littelfuse; Irating_A: 1.5A; SizeAreaWB_mm2: 10.92; Interrupt_AC: 50A; VAC_V: 50V; SizeZ_mm: 1.35; SizeX_mm: 3.2; SizeY_mm: 1.6; SizeArea_mm2: 5.12; Rtyp_Ohm: 0.1759; MeltingTyp: 0.50652
J19-J26 = CMP-0078526-1: Power Element Bush, M3, TH; Manufacturer: Wurth Elektronik; Gender: Female; Current_A: 50A; ContactFinish: Tin; CompType: Screw Terminal
K1 = CMP-0094655-1: Power Her 40A 4NO 1NC 12VDC; Manufacturer: Panasonic; TaMin_C: -40°C; Coil Power_W: 490mW; SizeZ_mm: 47.5mm; Coil Voltage_VDC: 12V; Coil Type: Non-Latching; AEC Qualified: No; Contact Form: 5PST-4NO-1NC; TaMax_C: +85°C; Standoff Height: 1.7mm; Coil Current_A: 333mA; Switching Power: 30W; Coil Resistance: 36Ω
Q10-Q14 = CMP-0000377-2: Transistor, NPN, 30 V, 0.1 A, SOT-23; Manufacturer: ON Semiconductor; TaMax_C: 150°C; Value2: 800; Value1: 0.1 A; Vcesat1_V: 700mV; SizeX_mm: 2.5; SizeY_mm: 3; TaMin_C: -55°C; IcRated_A: 100mA; CompType: BJT; SizeZ_mm: 1.1; Value: 30 V; SizeArea_mm2: 7.5; NPN: 1; Vceo_V: 30V; PNP: 0; AEC Category: Q101; SizeAreaWB_mm2: 14; U/M: EA
R192 R193 R195 R196 R200 R201 R203 R204 = CMP-0018654-3: RES, 30 k, 5%, 0.25 W, AEC-Q200 Grade 0, 1206; Manufacturer: Vishay-Dale; Power_W: 250mW; TempCo: 200 ppm/C; Value_Code: 30k0; Value: 30k; EIA_Code: E24; SizeX_mm: 3.2; SizeY_mm: 1.6; SizeZ_mm: 1.35; Value2: 0.25W; SizeArea_mm2: 5.12; AEC Qualified: Y; VDC_V: 200V; AEC Category: Q200; AEC Grade: 0
R194 R198 R202 R207 = CMP-0025930-5: RES, 560, 5%, 0.1 W, 0603; Manufacturer: Yageo; Power_W: 100mW; TempCo: 100 ppm/C; Value_Code: 560R; Value: 560; EIA_Code: E24; SizeX_mm: 1.6; SizeY_mm: 0.8; SizeZ_mm: 1; Value2: 0.1W; SizeArea_mm2: 1.28; AEC Qualified: N; VDC_V: 75V; AEC Category: Q200; SizeAreaWB_mm2: 4.68
R197 R199 R205 R208 = CMP-0025719-4: RES, 15 k, 5%, 0.1 W, AEC-Q200 Grade 0, 0603; Manufacturer: Vishay-Dale; Power_W: 100mW; TempCo: 200 ppm/C; Value_Code: 15k0; Value: 15k; EIA_Code: E24; SizeX_mm: 1.6; SizeY_mm: 0.8; SizeZ_mm: 1; Value2: 0.1W; SizeArea_mm2: 1.28; AEC Qualified: Y; VDC_V: 75V; AEC Category: Q200; AEC Grade: 0
R206 R209 = CMP-0081973-1: RES, 0, 0%, 0.25 W, AEC-Q200 Grade 0, 0603; Manufacturer: Vishay-Dale; SizeAreaWB_mm2: 4.68; SizeArea_mm2: 1.28; AEC Qualified: Y; AEC Category: Q200; Value: 0; SizeZ_mm: 1; SizeY_mm: 0.8; Power_W: 250mW; Value2: 0.25W; SizeX_mm: 1.6
R210 R218 = CMP-0025886-5: RES, 10 k, 5%, 0.1 W, 0603; Manufacturer: Yageo; Power_W: 100mW; TempCo: 100 ppm/C; Value_Code: 10k0; Value: 10k; EIA_Code: E24; SizeX_mm: 1.6; SizeY_mm: 0.8; SizeZ_mm: 1; Value2: 0.1W; SizeArea_mm2: 1.28; AEC Qualified: N; VDC_V: 75V; AEC Category: Q200; SizeAreaWB_mm2: 4.68
R211-R215 R217 = CMP-0023219-5: RES, 620, 1%, 0.1 W, 0603; Manufacturer: Yageo; Value: 620; Value_Code: 620R; Power_W: 100mW; Value2: 0.1W; VDC_V: 75V; TempCo: 100 ppm/C; SizeArea_mm2: 1.28; SizeX_mm: 1.6; SizeY_mm: 0.8; SizeZ_mm: 1; AEC Category: Q200; AEC Qualified: N; SizeAreaWB_mm2: 4.68
R216 R219-R222 = CMP-0022691-3: RES, 20.0 k, 1%, 0.1 W, AEC-Q200 Grade 0, 0603; Manufacturer: Panasonic; Value: 20.0k; Res_ohm: 20k; Value_Code: 20k0; Power_W: 100mW; Value2: 0.1W; VDC_V: 75V; TempCo: 100 ppm/C; SizeArea_mm2: 1.28; SizeX_mm: 1.6; SizeY_mm: 0.8; SizeZ_mm: 1; EIA_Code: E96; AEC Category: Q200; AEC Qualified: Y; AEC Grade: 0; U/M: EA
R800-R803 = CMP-0092692-1: RES SMD 0 OHM JUMPER 1/8W 0805; Manufacturer: Yageo; Res_ohm: 0; AEC Qualified: No; SizeZ_mm: 0.6mm; Value: 0; VDC_V: 150V; Power_W: 125mW; Tolerance_%: 1%
TP27 TP28 = CMP-0055140-1: Test Point, Miniature, Orange, TH; Manufacturer: Keystone; CNHeader: FALSE; Green_Lifecycle: Active; Green_REACh: Passed; ContactFinish: Silver; CT: TRUE
U33 U34 = CMP-0013034-2: ISO1212DBQR, DBQ00016A, DBQ0016A (SSOP-16); Manufacturer: Texas Instruments; SizeX_mm: 6; SizeY_mm: 10; CompType: IC; SizeZ_mm: 1.75; SizeArea_mm2: 60; SizeAreaWB_mm2: 96; U/M: EA
U35 = CMP-0090278-2: 18V, 1A H-bridge motor driver, PWM, PH/EN, ½ bridge control, with low power sleep mode; Manufacturer: Texas Instruments; Standoff Height: 0mm; TaMax_C: +125°C; Number Of Outputs: 2; AEC Qualified: No; TJmax_C: +150°C; SizeZ_mm: 0.6mm; AEC Category: Q200; TaMin_C: -40°C; Switching Frequency: 100kHz; Min Supply Voltage: 4.5V; Motor Type: Brushed; CompType: IC
U36 = CMP-0051576-2: Low-Power Single 2-Input Positive-AND Gate, DBV0005A (SOT-23-5); Manufacturer: Texas Instruments; 3-State Output: No; Output Type: CMOS; F @ Nom Voltage(Max)(Mhz): 100; Rating: Catalog; Voltage(Nom)(V): 0.8,1.2,1.5,1.8,2.5,3.3; Logic: True; Output Drive (IOL/IOH)(Max)(mA): 20/-20; tpd @ Nom Voltage(Max)(ns): 32.8,20.9,14.2,11,7.6,6.2; Bits(#): 1; ICC @ Nom Voltage(Max)(mA): 0.0009; Gate Type: AND; VCC(Max)(V): 3.6; VCC(Min)(V): 0.8; AEC Category: Q200; AEC Qualified: N; CompType: IC; SizeAreaWB_mm2: 14.82; SizeArea_mm2: 8.12; SizeX_mm: 2.8; SizeY_mm: 2.9; SizeZ_mm: 1.45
